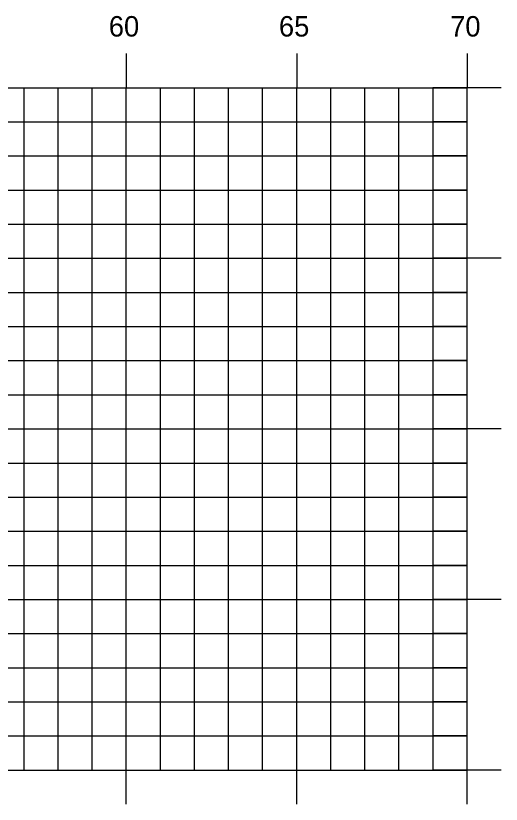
# Model space of a CAD drawing. Extents: x 859352 to 859522, y 366268 to 366378.
# Drawn here: x 859491.89 to 859506.13, y 366306.23 to 366329.35 of the extents above; entities that cross this region are included whole.
import ezdxf

# ---------------------------------------------------------------- set-up
doc = ezdxf.new("R2010")
doc.units = 0
for name, color, linetype in [('H_V ANNOTATION', 7, 'Continuous'), ('MAJOR', 7, 'Continuous'), ('MINOR', 7, 'Continuous')]:
    doc.layers.add(name, color=color, linetype=linetype)

msp = doc.modelspace()

# ---------------------------------------------------------------- linework, layer by layer
at = {"layer": 'MAJOR'}
for p, q in [((859495.129, 366328.238), (859495.129, 366327.236)), ((859500.129, 366328.238), (859500.129, 366327.236)), ((859505.129, 366328.238), (859505.129, 366327.236)), ((859365.129, 366327.236), (859505.129, 366327.236)), ((859365.129, 366327.236), (859505.129, 366327.236)), ((859495.129, 366307.236), (859495.129, 366327.236)), ((859500.129, 366307.236), (859500.129, 366327.236)), ((859506.131, 366327.236), (859504.127, 366327.236)), ((859505.129, 366307.236), (859505.129, 366327.236)), ((859505.129, 366307.236), (859505.129, 366327.236)), ((859365.129, 366322.236), (859505.129, 366322.236)), ((859506.131, 366322.236), (859504.127, 366322.236)), ((859365.129, 366317.236), (859505.129, 366317.236)), ((859506.131, 366317.236), (859504.127, 366317.236)), ((859365.129, 366312.236), (859505.129, 366312.236)), ((859506.131, 366312.236), (859504.127, 366312.236)), ((859365.129, 366307.236), (859505.129, 366307.236)), ((859365.129, 366307.236), (859505.129, 366307.236)), ((859495.129, 366306.234), (859495.129, 366307.236)), ((859500.129, 366306.234), (859500.129, 366307.236)), ((859506.131, 366307.236), (859504.127, 366307.236)), ((859505.129, 366306.234), (859505.129, 366307.236))]:
    msp.add_line(p, q, dxfattribs=at)
at = {"layer": 'MINOR'}
for p, q in [((859492.129, 366307.236), (859492.129, 366327.236)), ((859493.129, 366307.236), (859493.129, 366327.236)), ((859494.129, 366307.236), (859494.129, 366327.236)), ((859496.129, 366307.236), (859496.129, 366327.236)), ((859497.129, 366307.236), (859497.129, 366327.236)), ((859498.129, 366307.236), (859498.129, 366327.236)), ((859499.129, 366307.236), (859499.129, 366327.236)), ((859501.129, 366307.236), (859501.129, 366327.236)), ((859502.129, 366307.236), (859502.129, 366327.236)), ((859503.129, 366307.236), (859503.129, 366327.236)), ((859504.129, 366307.236), (859504.129, 366327.236)), ((859365.129, 366326.236), (859505.129, 366326.236)), ((859505.129, 366326.236), (859504.127, 366326.236)), ((859365.129, 366325.236), (859505.129, 366325.236)), ((859505.129, 366325.236), (859504.127, 366325.236)), ((859365.129, 366324.236), (859505.129, 366324.236)), ((859505.129, 366324.236), (859504.127, 366324.236)), ((859365.129, 366323.236), (859505.129, 366323.236)), ((859505.129, 366323.236), (859504.127, 366323.236)), ((859365.129, 366321.236), (859505.129, 366321.236)), ((859505.129, 366321.236), (859504.127, 366321.236)), ((859365.129, 366320.236), (859505.129, 366320.236)), ((859505.129, 366320.236), (859504.127, 366320.236)), ((859365.129, 366319.236), (859505.129, 366319.236)), ((859505.129, 366319.236), (859504.127, 366319.236)), ((859365.129, 366318.236), (859505.129, 366318.236)), ((859505.129, 366318.236), (859504.127, 366318.236)), ((859365.129, 366316.236), (859505.129, 366316.236)), ((859505.129, 366316.236), (859504.127, 366316.236)), ((859365.129, 366315.236), (859505.129, 366315.236)), ((859505.129, 366315.236), (859504.127, 366315.236)), ((859365.129, 366314.236), (859505.129, 366314.236)), ((859505.129, 366314.236), (859504.127, 366314.236)), ((859365.129, 366313.236), (859505.129, 366313.236)), ((859505.129, 366313.236), (859504.127, 366313.236)), ((859365.129, 366311.236), (859505.129, 366311.236)), ((859505.129, 366311.236), (859504.127, 366311.236)), ((859365.129, 366310.236), (859505.129, 366310.236)), ((859505.129, 366310.236), (859504.127, 366310.236)), ((859365.129, 366309.236), (859505.129, 366309.236)), ((859505.129, 366309.236), (859504.127, 366309.236)), ((859365.129, 366308.236), (859505.129, 366308.236)), ((859505.129, 366308.236), (859504.127, 366308.236))]:
    msp.add_line(p, q, dxfattribs=at)

# ---------------------------------------------------------------- texts
at = {"layer": 'H_V ANNOTATION'}
for s, p in [('60', (859494.616, 366328.736)), ('65', (859499.608, 366328.736)), ('70', (859504.631, 366328.736))]:
    msp.add_text(s, height=0.6, dxfattribs=at).set_placement(p)

doc.saveas('drawing.dxf')
